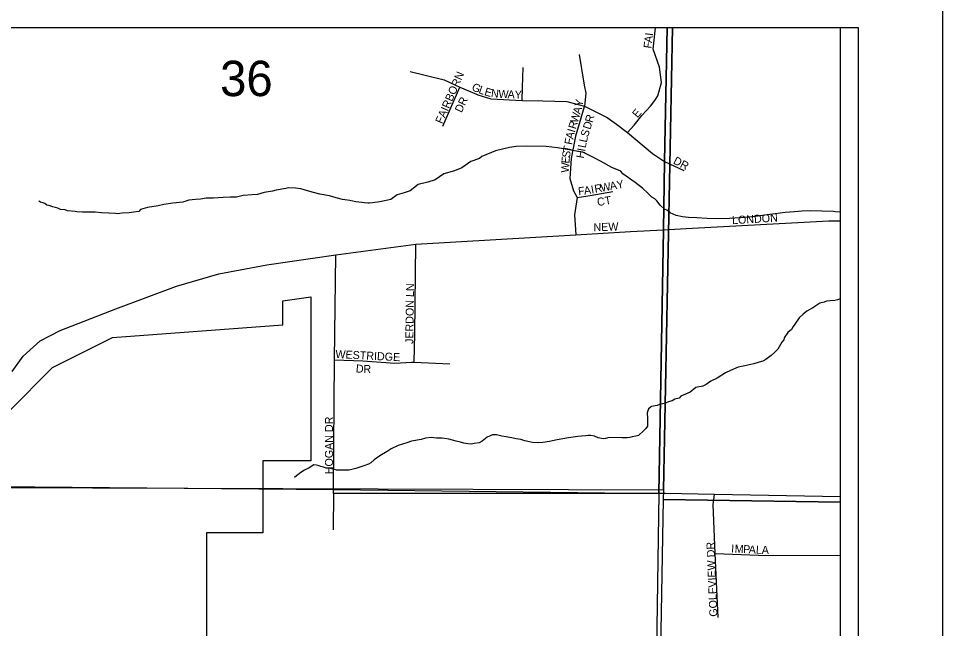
# Model space of a CAD drawing. Extents: x 0 to 34, y -2.3 to 22.
# Drawn here: x 7.907 to 9, y 20.189 to 20.911 of the extents above; entities that cross this region are included whole.
import ezdxf

# ---------------------------------------------------------------- set-up
doc = ezdxf.new("R2010")
doc.units = 0
for name, color, linetype in [('GM_X_City_Street', 7, 'Continuous'), ('GM_X_City_Street_Text', 7, 'Continuous'), ('GM_X_Corporation', 7, 'Continuous'), ('GM_X_County', 7, 'Continuous'), ('GM_X_Minor_River', 7, 'Continuous'), ('GM_X_Section', 7, 'Continuous'), ('GM_X_Section_Text', 7, 'Continuous'), ('GM_X_Township', 7, 'Continuous'), ('SH_Data', 7, 'Continuous')]:
    doc.layers.add(name, color=color, linetype=linetype)

msp = doc.modelspace()

# ---------------------------------------------------------------- linework, layer by layer
at = {"layer": 'GM_X_City_Street'}
for p, q in [((8.6574, 20.8744), (8.6605, 20.8994)), ((8.6652, 20.8528), (8.6574, 20.8744)), ((8.5702, 20.8678), (8.576, 20.8316)), ((8.5028, 20.829), (8.5039, 20.8527)), ((8.6674, 20.8347), (8.6652, 20.8528)), ((8.3702, 20.848), (8.3877, 20.8434)), ((8.3877, 20.8434), (8.4101, 20.8381)), ((8.4101, 20.8381), (8.429, 20.8292)), ((8.576, 20.8316), (8.5778, 20.8223)), ((8.6631, 20.819), (8.6674, 20.8347)), ((8.4088, 20.7833), (8.429, 20.8292)), ((8.429, 20.8292), (8.4486, 20.821)), ((8.4486, 20.821), (8.4503, 20.8203)), ((8.4503, 20.8203), (8.4654, 20.8157)), ((8.5026, 20.8135), (8.5028, 20.829)), ((8.5778, 20.8223), (8.5762, 20.8067)), ((8.4654, 20.8157), (8.5026, 20.8135)), ((8.5026, 20.8135), (8.527, 20.8132)), ((8.527, 20.8132), (8.5554, 20.8123)), ((8.5554, 20.8123), (8.5762, 20.8067)), ((8.6543, 20.807), (8.6596, 20.8137)), ((8.6596, 20.8137), (8.6631, 20.819)), ((8.576, 20.8062), (8.5702, 20.786)), ((8.5762, 20.8067), (8.576, 20.8062)), ((8.5762, 20.8067), (8.6033, 20.7935)), ((8.6443, 20.7959), (8.6543, 20.807)), ((8.6033, 20.7935), (8.6144, 20.7857)), ((8.6352, 20.7844), (8.6443, 20.7959)), ((8.5702, 20.786), (8.5658, 20.7713)), ((8.6144, 20.7857), (8.6272, 20.7758)), ((8.6272, 20.7758), (8.6352, 20.7844)), ((8.5658, 20.7713), (8.5605, 20.7447)), ((8.6272, 20.7758), (8.6567, 20.7507)), ((8.5605, 20.7447), (8.5591, 20.7212)), ((8.6567, 20.7507), (8.6712, 20.7412)), ((8.6712, 20.7412), (8.694, 20.7307)), ((8.5591, 20.7212), (8.5634, 20.7066)), ((8.5634, 20.7066), (8.5676, 20.6988)), ((8.5676, 20.6988), (8.5831, 20.7012)), ((8.5831, 20.7012), (8.6097, 20.7059)), ((8.5676, 20.6988), (8.5645, 20.6784)), ((8.5645, 20.6784), (8.5659, 20.6546)), ((8.6965, 20.6619), (8.8655, 20.671)), ((8.8655, 20.671), (8.8792, 20.6711)), ((8.5659, 20.6546), (8.6309, 20.6585)), ((8.6309, 20.6585), (8.6698, 20.6604)), ((8.6698, 20.6604), (8.6965, 20.6619)), ((8.3767, 20.6434), (8.5659, 20.6546)), ((8.2822, 20.631), (8.3767, 20.6434)), ((8.3755, 20.5374), (8.3767, 20.6434)), ((8.2006, 20.619), (8.2822, 20.631)), ((8.2806, 20.5066), (8.2822, 20.631)), ((8.1438, 20.6083), (8.2006, 20.619)), ((8.0937, 20.5939), (8.1438, 20.6083)), ((8.0216, 20.5669), (8.0937, 20.5939)), ((7.956, 20.5414), (8.0216, 20.5669)), ((7.9323, 20.5292), (7.956, 20.5414)), ((8.3749, 20.5039), (8.3755, 20.5374)), ((7.9119, 20.511), (7.9323, 20.5292)), ((7.8992, 20.4928), (7.9119, 20.511)), ((8.2793, 20.353), (8.2806, 20.5066)), ((8.2806, 20.5066), (8.3141, 20.5054)), ((8.3141, 20.5054), (8.3518, 20.5028)), ((8.3518, 20.5028), (8.3715, 20.5037)), ((8.3715, 20.5037), (8.3749, 20.5039)), ((8.3749, 20.5039), (8.417, 20.5019)), ((8.2793, 20.3485), (8.2793, 20.353)), ((8.2793, 20.3485), (8.279, 20.3055)), ((8.6643, 20.3486), (8.2793, 20.3485)), ((8.6721, 20.3484), (8.6643, 20.3486)), ((8.7301, 20.3472), (8.6721, 20.3484)), ((8.7285, 20.3355), (8.7301, 20.3472)), ((8.8792, 20.3445), (8.7301, 20.3472)), ((8.731, 20.2773), (8.7285, 20.3355)), ((8.7344, 20.2018), (8.731, 20.2773)), ((8.731, 20.2773), (8.7824, 20.2756)), ((8.7824, 20.2756), (8.8792, 20.275))]:
    msp.add_line(p, q, dxfattribs=at)
at = {"layer": 'GM_X_Corporation'}
for points in [[(8.8792, 19.7101), (8.8792, 20.8994), (7.6158, 20.8994)], [(7.8951, 20.4454), (7.9466, 20.4977), (8.0178, 20.5329), (8.2192, 20.5482), (8.2192, 20.5766), (8.2523, 20.5813), (8.2523, 20.3872), (8.1955, 20.3872), (8.1955, 20.302), (8.1292, 20.302), (8.1292, 19.6203), (8.5269, 19.6202), (8.5269, 19.9753), (8.7542, 19.9753), (8.7527, 19.7449), (8.8792, 19.7101)]]:
    msp.add_lwpolyline(points, dxfattribs=at)
at = {"layer": 'GM_X_County'}
for p, q in [((8.8792, 20.8994), (2.0792, 20.8994)), ((8.8792, 14.574), (8.8792, 20.8994))]:
    msp.add_line(p, q, dxfattribs=at)
at = {"layer": 'GM_X_Minor_River'}
for p, q in [((8.4709, 20.754), (8.4548, 20.7472)), ((8.4877, 20.7578), (8.4709, 20.754)), ((8.4953, 20.7591), (8.4877, 20.7578)), ((8.5075, 20.7595), (8.4953, 20.7591)), ((8.531, 20.7589), (8.5075, 20.7595)), ((8.5442, 20.7575), (8.531, 20.7589)), ((8.556, 20.7557), (8.5442, 20.7575)), ((8.5647, 20.7539), (8.556, 20.7557)), ((8.5745, 20.7522), (8.5647, 20.7539)), ((8.4521, 20.745), (8.4418, 20.7415)), ((8.4548, 20.7472), (8.4521, 20.745)), ((8.5861, 20.7466), (8.5745, 20.7522)), ((8.5951, 20.7418), (8.5861, 20.7466)), ((8.4313, 20.7338), (8.4225, 20.7302)), ((8.4418, 20.7415), (8.4313, 20.7338)), ((8.6086, 20.7342), (8.5951, 20.7418)), ((8.6195, 20.7298), (8.6086, 20.7342)), ((8.4099, 20.7268), (8.3995, 20.7198)), ((8.4225, 20.7302), (8.4099, 20.7268)), ((8.6217, 20.7267), (8.6195, 20.7298)), ((8.6363, 20.7165), (8.6217, 20.7267)), ((8.2262, 20.7102), (8.2231, 20.7095)), ((8.2345, 20.7096), (8.2262, 20.7102)), ((8.3796, 20.7143), (8.3699, 20.7066)), ((8.3911, 20.717), (8.3796, 20.7143)), ((8.3995, 20.7198), (8.3911, 20.717)), ((8.6448, 20.7098), (8.6363, 20.7165)), ((8.1644, 20.6993), (8.1572, 20.6991)), ((8.1724, 20.701), (8.1644, 20.6993)), ((8.1831, 20.7018), (8.1724, 20.701)), ((8.1895, 20.7024), (8.1831, 20.7018)), ((8.1972, 20.7045), (8.1895, 20.7024)), ((8.2071, 20.7062), (8.1972, 20.7045)), ((8.2113, 20.7076), (8.2071, 20.7062)), ((8.2231, 20.7095), (8.2113, 20.7076)), ((8.2406, 20.7091), (8.2345, 20.7096)), ((8.2485, 20.7066), (8.2406, 20.7091)), ((8.2556, 20.7045), (8.2485, 20.7066)), ((8.2632, 20.7028), (8.2556, 20.7045)), ((8.2745, 20.7007), (8.2632, 20.7028)), ((8.2787, 20.6994), (8.2745, 20.7007)), ((8.2824, 20.6982), (8.2787, 20.6994)), ((8.3546, 20.7017), (8.3473, 20.6965)), ((8.3631, 20.7041), (8.3546, 20.7017)), ((8.3699, 20.7066), (8.3631, 20.7041)), ((8.6515, 20.7036), (8.6448, 20.7098)), ((8.656, 20.6993), (8.6515, 20.7036)), ((8.6597, 20.697), (8.656, 20.6993)), ((7.9327, 20.6934), (7.9305, 20.6942)), ((7.9354, 20.6926), (7.9327, 20.6934)), ((7.9376, 20.6918), (7.9354, 20.6926)), ((7.9402, 20.6898), (7.9376, 20.6918)), ((7.944, 20.689), (7.9402, 20.6898)), ((7.9466, 20.6878), (7.944, 20.689)), ((8.0719, 20.6888), (8.0594, 20.6868)), ((8.0784, 20.6905), (8.0719, 20.6888)), ((8.0891, 20.6921), (8.0784, 20.6905)), ((8.1009, 20.6933), (8.0891, 20.6921)), ((8.1081, 20.6954), (8.1009, 20.6933)), ((8.1161, 20.6963), (8.1081, 20.6954)), ((8.1218, 20.6966), (8.1161, 20.6963)), ((8.1287, 20.6979), (8.1218, 20.6966)), ((8.1374, 20.6981), (8.1287, 20.6979)), ((8.1428, 20.6983), (8.1374, 20.6981)), ((8.1488, 20.6989), (8.1428, 20.6983)), ((8.1572, 20.6991), (8.1488, 20.6989)), ((8.29, 20.6965), (8.2824, 20.6982)), ((8.2987, 20.6951), (8.29, 20.6965)), ((8.3059, 20.6938), (8.2987, 20.6951)), ((8.3127, 20.6929), (8.3059, 20.6938)), ((8.3161, 20.6924), (8.3127, 20.6929)), ((8.3199, 20.6919), (8.3161, 20.6924)), ((8.3221, 20.6919), (8.3199, 20.6919)), ((8.3256, 20.6925), (8.3221, 20.6919)), ((8.3343, 20.6938), (8.3256, 20.6925)), ((8.3473, 20.6965), (8.3343, 20.6938)), ((8.6619, 20.6946), (8.6597, 20.697)), ((8.666, 20.6896), (8.6619, 20.6946)), ((8.6712, 20.6849), (8.666, 20.6896)), ((7.9504, 20.6869), (7.9466, 20.6878)), ((7.9531, 20.6861), (7.9504, 20.6869)), ((7.9564, 20.6845), (7.9531, 20.6861)), ((7.9617, 20.684), (7.9564, 20.6845)), ((7.9644, 20.6831), (7.9617, 20.684)), ((7.9735, 20.6822), (7.9644, 20.6831)), ((7.9757, 20.6817), (7.9735, 20.6822)), ((7.9822, 20.6812), (7.9757, 20.6817)), ((7.986, 20.6815), (7.9822, 20.6812)), ((7.9894, 20.6814), (7.986, 20.6815)), ((7.9936, 20.6813), (7.9894, 20.6814)), ((7.9973, 20.6812), (7.9936, 20.6813)), ((8.0049, 20.6806), (7.9973, 20.6812)), ((8.0133, 20.68), (8.0049, 20.6806)), ((8.0212, 20.6798), (8.0133, 20.68)), ((8.0239, 20.6794), (8.0212, 20.6798)), ((8.0292, 20.68), (8.0239, 20.6794)), ((8.0376, 20.6805), (8.0292, 20.68)), ((8.0429, 20.6812), (8.0376, 20.6805)), ((8.049, 20.6821), (8.0429, 20.6812)), ((8.0509, 20.6844), (8.049, 20.6821)), ((8.0594, 20.6868), (8.0509, 20.6844)), ((8.6746, 20.6833), (8.6712, 20.6849)), ((8.6779, 20.6806), (8.6746, 20.6833)), ((8.685, 20.6774), (8.6779, 20.6806)), ((8.6922, 20.6757), (8.685, 20.6774)), ((8.7925, 20.6784), (8.7811, 20.6768)), ((8.802, 20.6793), (8.7925, 20.6784)), ((8.8138, 20.6809), (8.802, 20.6793)), ((8.8248, 20.6818), (8.8138, 20.6809)), ((8.8336, 20.6827), (8.8248, 20.6818)), ((8.8435, 20.6828), (8.8336, 20.6827)), ((8.8711, 20.6821), (8.8435, 20.6828)), ((8.8734, 20.6817), (8.8711, 20.6821)), ((8.8792, 20.6813), (8.8734, 20.6817)), ((8.6994, 20.6751), (8.6922, 20.6757)), ((8.7093, 20.6745), (8.6994, 20.6751)), ((8.7214, 20.6738), (8.7093, 20.6745)), ((8.7354, 20.6735), (8.7214, 20.6738)), ((8.748, 20.6739), (8.7354, 20.6735)), ((8.7609, 20.6747), (8.748, 20.6739)), ((8.7708, 20.6756), (8.7609, 20.6747)), ((8.7811, 20.6768), (8.7708, 20.6756)), ((8.8502, 20.5705), (8.8464, 20.568)), ((8.8549, 20.5738), (8.8502, 20.5705)), ((8.8598, 20.5748), (8.8549, 20.5738)), ((8.8629, 20.5759), (8.8598, 20.5748)), ((8.8671, 20.5765), (8.8629, 20.5759)), ((8.8724, 20.5768), (8.8671, 20.5765)), ((8.8758, 20.5775), (8.8724, 20.5768)), ((8.8792, 20.5787), (8.8758, 20.5775)), ((8.8352, 20.5607), (8.8305, 20.5563)), ((8.8395, 20.5644), (8.8352, 20.5607)), ((8.8464, 20.568), (8.8395, 20.5644)), ((8.8231, 20.5462), (8.8211, 20.5425)), ((8.8254, 20.5488), (8.8231, 20.5462)), ((8.8305, 20.5563), (8.8254, 20.5488)), ((8.8168, 20.5388), (8.8125, 20.5325)), ((8.8211, 20.5425), (8.8168, 20.5388)), ((8.8097, 20.5276), (8.805, 20.5194)), ((8.8121, 20.5302), (8.8097, 20.5276)), ((8.8125, 20.5325), (8.8121, 20.5302)), ((8.8011, 20.5153), (8.7972, 20.5116)), ((8.805, 20.5194), (8.8011, 20.5153)), ((8.783, 20.5037), (8.7769, 20.5019)), ((8.7872, 20.5051), (8.783, 20.5037)), ((8.791, 20.5072), (8.7872, 20.5051)), ((8.7972, 20.5116), (8.791, 20.5072)), ((8.749, 20.4939), (8.7432, 20.4914)), ((8.7582, 20.4979), (8.749, 20.4939)), ((8.7662, 20.4995), (8.7582, 20.4979)), ((8.7769, 20.5019), (8.7662, 20.4995)), ((8.7259, 20.4812), (8.7205, 20.4776)), ((8.7332, 20.4848), (8.7259, 20.4812)), ((8.7432, 20.4914), (8.7332, 20.4848)), ((8.7082, 20.4737), (8.7013, 20.4682)), ((8.7162, 20.4754), (8.7082, 20.4737)), ((8.7205, 20.4776), (8.7162, 20.4754)), ((8.6832, 20.46), (8.6802, 20.4582)), ((8.6882, 20.4614), (8.6832, 20.46)), ((8.6905, 20.4636), (8.6882, 20.4614)), ((8.7013, 20.4682), (8.6905, 20.4636)), ((8.6522, 20.4486), (8.6506, 20.4438)), ((8.6557, 20.4512), (8.6522, 20.4486)), ((8.6622, 20.4526), (8.6557, 20.4512)), ((8.6649, 20.4536), (8.6622, 20.4526)), ((8.6687, 20.4547), (8.6649, 20.4536)), ((8.6721, 20.4553), (8.6687, 20.4547)), ((8.6756, 20.4568), (8.6721, 20.4553)), ((8.6802, 20.4582), (8.6756, 20.4568)), ((8.6506, 20.4438), (8.6508, 20.4373)), ((8.6508, 20.4373), (8.6507, 20.4328)), ((8.651, 20.4282), (8.649, 20.4252)), ((8.6507, 20.4328), (8.651, 20.4282)), ((8.4612, 20.4152), (8.4554, 20.4104)), ((8.4674, 20.4177), (8.4612, 20.4152)), ((8.4697, 20.418), (8.4674, 20.4177)), ((8.4723, 20.418), (8.4697, 20.418)), ((8.4784, 20.4163), (8.4723, 20.418)), ((8.4836, 20.4154), (8.4784, 20.4163)), ((8.4874, 20.4146), (8.4836, 20.4154)), ((8.5683, 20.4159), (8.5576, 20.4143)), ((8.5729, 20.4162), (8.5683, 20.4159)), ((8.5774, 20.4168), (8.5729, 20.4162)), ((8.5805, 20.4171), (8.5774, 20.4168)), ((8.5839, 20.417), (8.5805, 20.4171)), ((8.588, 20.4162), (8.5839, 20.417)), ((8.5926, 20.4145), (8.588, 20.4162)), ((8.6328, 20.4154), (8.6301, 20.4147)), ((8.637, 20.4164), (8.6328, 20.4154)), ((8.6404, 20.4171), (8.637, 20.4164)), ((8.6463, 20.4227), (8.6404, 20.4171)), ((8.649, 20.4252), (8.6463, 20.4227)), ((8.3559, 20.4054), (8.3474, 20.4011)), ((8.3662, 20.4085), (8.3559, 20.4054)), ((8.3715, 20.4103), (8.3662, 20.4085)), ((8.383, 20.4123), (8.3715, 20.4103)), ((8.3883, 20.414), (8.383, 20.4123)), ((8.3948, 20.4146), (8.3883, 20.414)), ((8.4012, 20.4141), (8.3948, 20.4146)), ((8.405, 20.414), (8.4012, 20.4141)), ((8.4081, 20.4139), (8.405, 20.414)), ((8.4107, 20.4135), (8.4081, 20.4139)), ((8.4156, 20.4126), (8.4107, 20.4135)), ((8.4243, 20.4105), (8.4156, 20.4126)), ((8.4296, 20.4092), (8.4243, 20.4105)), ((8.4337, 20.408), (8.4296, 20.4092)), ((8.4383, 20.4071), (8.4337, 20.408)), ((8.4428, 20.407), (8.4383, 20.4071)), ((8.4459, 20.4077), (8.4428, 20.407)), ((8.4516, 20.4083), (8.4459, 20.4077)), ((8.4554, 20.4104), (8.4516, 20.4083)), ((8.4905, 20.4145), (8.4874, 20.4146)), ((8.4954, 20.4132), (8.4905, 20.4145)), ((8.501, 20.4123), (8.4954, 20.4132)), ((8.5059, 20.4107), (8.501, 20.4123)), ((8.515, 20.4089), (8.5059, 20.4107)), ((8.5222, 20.4084), (8.515, 20.4089)), ((8.5271, 20.4086), (8.5222, 20.4084)), ((8.5351, 20.4099), (8.5271, 20.4086)), ((8.5439, 20.412), (8.5351, 20.4099)), ((8.5576, 20.4143), (8.5439, 20.412)), ((8.5986, 20.4133), (8.5926, 20.4145)), ((8.6013, 20.4136), (8.5986, 20.4133)), ((8.6055, 20.4146), (8.6013, 20.4136)), ((8.621, 20.4142), (8.6055, 20.4146)), ((8.6271, 20.4144), (8.621, 20.4142)), ((8.6301, 20.4147), (8.6271, 20.4144)), ((8.3428, 20.3981), (8.3343, 20.3931)), ((8.3474, 20.4011), (8.3428, 20.3981)), ((8.2562, 20.3822), (8.2505, 20.3789)), ((8.2593, 20.3821), (8.2562, 20.3822)), ((8.3208, 20.3832), (8.3162, 20.3814)), ((8.3235, 20.3846), (8.3208, 20.3832)), ((8.3274, 20.3883), (8.3235, 20.3846)), ((8.3343, 20.3931), (8.3274, 20.3883)), ((8.2408, 20.3734), (8.2354, 20.3694)), ((8.2451, 20.376), (8.2408, 20.3734)), ((8.2505, 20.3789), (8.2451, 20.376)), ((8.2623, 20.3812), (8.2593, 20.3821)), ((8.2645, 20.3804), (8.2623, 20.3812)), ((8.2676, 20.3796), (8.2645, 20.3804)), ((8.2706, 20.3784), (8.2676, 20.3796)), ((8.2759, 20.3779), (8.2706, 20.3784)), ((8.2808, 20.377), (8.2759, 20.3779)), ((8.283, 20.3762), (8.2808, 20.377)), ((8.2937, 20.3759), (8.283, 20.3762)), ((8.2978, 20.3762), (8.2937, 20.3759)), ((8.3009, 20.3769), (8.2978, 20.3762)), ((8.3059, 20.3782), (8.3009, 20.3769)), ((8.3128, 20.3803), (8.3059, 20.3782)), ((8.3162, 20.3814), (8.3128, 20.3803)), ((8.2354, 20.3694), (8.2331, 20.3672))]:
    msp.add_line(p, q, dxfattribs=at)
at = {"layer": 'GM_X_Section'}
for p, q in [((8.6806, 20.8994), (7.6777, 20.8994)), ((8.6806, 20.8994), (8.67, 20.3528)), ((8.67, 20.3528), (8.6806, 20.8994)), ((8.8792, 20.8994), (8.6806, 20.8994)), ((8.8792, 20.3383), (8.8792, 20.8994)), ((7.6696, 20.3563), (8.67, 20.3528)), ((7.6696, 20.3563), (8.67, 20.3528)), ((8.67, 20.3528), (8.6694, 20.3414)), ((8.67, 20.3528), (8.6694, 20.3414)), ((8.6694, 20.3414), (8.6506, 19.3353)), ((8.6694, 20.3414), (8.6506, 19.3353)), ((8.6694, 20.3414), (8.8792, 20.3383)), ((8.8792, 20.3383), (8.6694, 20.3414)), ((8.8792, 19.3331), (8.8792, 20.3383))]:
    msp.add_line(p, q, dxfattribs=at)
at = {"layer": 'GM_X_Township'}
for p, q in [((8.674, 20.8994), (2.6175, 20.8994)), ((8.6712, 20.7412), (8.674, 20.8994)), ((8.674, 20.8994), (8.6712, 20.7412)), ((8.8792, 20.8994), (8.674, 20.8994)), ((8.8792, 17.9482), (8.8792, 20.8994)), ((8.6698, 20.6604), (8.6712, 20.7412)), ((8.6712, 20.7412), (8.6698, 20.6604)), ((8.6643, 20.3485), (8.6698, 20.6604)), ((8.6698, 20.6604), (8.6643, 20.3485)), ((7.8061, 20.3576), (8.2793, 20.353)), ((7.8061, 20.3576), (8.2793, 20.353)), ((8.2793, 20.353), (8.6643, 20.3485)), ((8.2793, 20.353), (8.6643, 20.3485)), ((8.6643, 20.3485), (8.6549, 19.7576)), ((8.6643, 20.3485), (8.6549, 19.7576))]:
    msp.add_line(p, q, dxfattribs=at)
at = {"layer": 'SH_Data'}
for p, q in [((9, 21), (9, 14)), ((2.1, 20.9), (8.9, 20.9)), ((8.9, 20.9), (8.9, 14.1))]:
    msp.add_line(p, q, dxfattribs=at)

# ---------------------------------------------------------------- texts
at = {"layer": 'GM_X_City_Street_Text'}
for s, rotation, p in [('A', 82.5017, (8.6562, 20.8813)), ('I', 82.5007, (8.6573, 20.8896)), ('F', 82.492, (8.6554, 20.8747)), ('FAIRBORN', 66.3704, (8.408, 20.7852)), ('G', 336.1485, (8.4421, 20.8261)), ('L', 340.0611, (8.4503, 20.8225)), ('E', 343.6183, (8.4572, 20.82)), ('N', 353.0899, (8.4653, 20.8178)), ('W', 357.5877, (8.4744, 20.8167)), ('A', 357.5076, (8.4852, 20.8163)), ('Y', 357.544, (8.4935, 20.8159)), ('DR', 64.8032, (8.4309, 20.7984)), ('Y', 79.5969, (8.5739, 20.8057)), ('W', 73.2589, (8.5681, 20.7862)), ('A', 73.496, (8.5713, 20.7966)), ('E', 50.2016, (8.6391, 20.7923)), ('R', 73.2891, (8.566, 20.779)), ('D', 72.7831, (8.5832, 20.7785)), ('R', 73.4827, (8.5857, 20.7866)), ('I', 73.4724, (8.5648, 20.775)), ('S', 72.6492, (8.5804, 20.7696)), ('F', 79.2847, (8.5617, 20.7606)), ('A', 76.5999, (8.5629, 20.7671)), ('L', 77.5542, (8.579, 20.7633)), ('T', 79.3787, (8.56, 20.7516)), ('H', 80.1819, (8.5756, 20.7445)), ('I', 79.9629, (8.577, 20.7527)), ('L', 79.132, (8.5777, 20.7568)), ('E', 85.2953, (8.5584, 20.7387)), ('S', 80.7398, (8.5589, 20.7451)), ('DR', 332.1033, (8.6805, 20.7394)), ('W', 87.0058, (8.5579, 20.7279)), ('F', 7.2047, (8.5694, 20.7013)), ('A', 8.0782, (8.5762, 20.7021)), ('I', 9.9968, (8.5848, 20.7033)), ('R', 10.3852, (8.589, 20.7041)), ('W', 10.4041, (8.5963, 20.7054)), ('A', 10.4186, (8.607, 20.7074)), ('Y', 10.3948, (8.6152, 20.7089)), ('CT', 9.4564, (8.592, 20.6885)), ('LONDON', 3.3191, (8.7512, 20.6671)), ('NEW', 1.789, (8.5871, 20.6588)), ('JERDON LN', 89.2359, (8.3737, 20.5253)), ('WESTRIDGE', 357.1392, (8.2814, 20.5088)), ('D', 354.5716, (8.3054, 20.4919)), ('R', 359.2599, (8.3146, 20.4911)), ('HOGAN DR', 90, (8.2787, 20.3712)), ('GOLFVIEW DR', 92.4109, (8.7337, 20.2028)), ('I', 357.1791, (8.7497, 20.2787)), ('M', 357.1899, (8.7539, 20.2785)), ('P', 357.1847, (8.7639, 20.278)), ('A', 357.1894, (8.7705, 20.2776)), ('L', 358.4114, (8.7791, 20.2772)), ('A', 359.7337, (8.786, 20.277))]:
    msp.add_text(s, height=0.00947, rotation=rotation, dxfattribs=at).set_placement(p)
at = {"layer": 'GM_X_Section_Text'}
msp.add_text('36', height=0.04186, rotation=0, dxfattribs=at).set_placement((8.1451, 20.8187))

doc.saveas('drawing.dxf')
